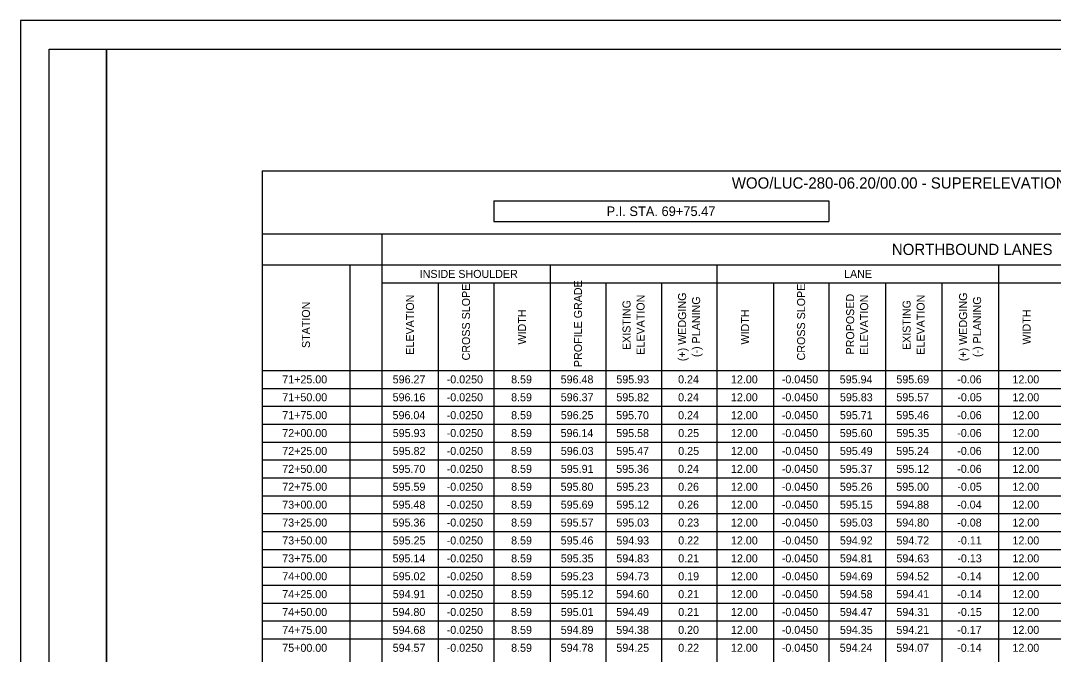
# Model space of a CAD drawing. Extents: x 0 to 34, y 0 to 22.
# Drawn here: x 0 to 18.07, y 10.92 to 22 of the extents above; entities that cross this region are included whole.
import ezdxf

# ---------------------------------------------------------------- set-up
doc = ezdxf.new("R2010")
doc.units = 0
for name, color, linetype in [('SH_Border', 7, 'Continuous'), ('SH_Cut_Line', 7, 'Continuous'), ('SH_Text', 7, 'Continuous')]:
    doc.layers.add(name, color=color, linetype=linetype)

msp = doc.modelspace()

# ---------------------------------------------------------------- linework, layer by layer
at = {"layer": 'SH_Border'}
for points in [[(0.5, 21.5), (1.5, 21.5), (1.5, 0.5), (0.5, 0.5)], [(1.5, 21.5), (33.5, 21.5), (33.5, 0.5), (1.5, 0.5)]]:
    msp.add_lwpolyline(points, close=True, dxfattribs=at)
at = {"layer": 'SH_Cut_Line'}
msp.add_lwpolyline([(0, 0), (34, 0), (34, 22), (0, 22)], close=True, dxfattribs=at)
at = {"layer": 'SH_Text'}
for p, q in [((4.225, 19.375), (29.277, 19.375)), ((4.225, 19.375), (4.225, 2.624)), ((8.277, 18.848), (14.14, 18.848)), ((8.277, 18.848), (8.277, 18.486)), ((14.14, 18.848), (14.14, 18.486)), ((8.277, 18.486), (14.14, 18.486)), ((4.225, 18.271), (29.277, 18.271)), ((6.317, 18.271), (6.317, 2.624)), ((4.225, 17.728), (29.277, 17.728)), ((5.757, 17.728), (5.757, 2.624)), ((9.265, 17.728), (9.265, 2.624)), ((12.18, 17.728), (12.18, 2.624)), ((17.105, 17.728), (17.105, 2.624)), ((6.317, 17.415), (26.954, 17.415)), ((7.305, 17.415), (7.305, 2.624)), ((8.277, 17.415), (8.277, 2.624)), ((10.237, 17.415), (10.237, 2.624)), ((11.209, 17.415), (11.209, 2.624)), ((13.169, 17.415), (13.169, 2.624)), ((14.14, 17.415), (14.14, 2.624)), ((15.129, 17.415), (15.129, 2.624)), ((16.117, 17.415), (16.117, 2.624)), ((4.225, 15.883), (29.277, 15.883)), ((4.225, 15.57), (29.277, 15.57)), ((4.225, 15.257), (29.277, 15.257)), ((4.225, 14.944), (29.277, 14.944)), ((4.225, 14.631), (29.277, 14.631)), ((4.225, 14.319), (29.277, 14.319)), ((4.225, 14.006), (29.277, 14.006)), ((4.225, 13.693), (29.277, 13.693)), ((4.225, 13.38), (29.277, 13.38)), ((4.225, 13.067), (29.277, 13.067)), ((4.225, 12.754), (29.277, 12.754)), ((4.225, 12.441), (29.277, 12.441)), ((4.225, 12.128), (29.277, 12.128)), ((4.225, 11.815), (29.277, 11.815)), ((4.225, 11.502), (29.277, 11.502)), ((4.225, 11.189), (29.277, 11.189))]:
    msp.add_line(p, q, dxfattribs=at)

# ---------------------------------------------------------------- texts
for s, height, p in [('WOO/LUC-280-06.20/00.00 - SUPERELEVATION TABLE', 0.196, (12.442, 19.063)), ('P.I. STA. 69+75.47', 0.168, (10.251, 18.583)), ('NORTHBOUND LANES', 0.196, (15.242, 17.902)), ('INSIDE SHOULDER', 0.14, (6.981, 17.501)), ('LANE', 0.14, (14.406, 17.501)), ('71+25.00', 0.14, (4.577, 15.657)), ('596.27', 0.14, (6.509, 15.657)), ('-0.0250', 0.14, (7.454, 15.657)), ('8.59', 0.14, (8.581, 15.657)), ('596.48', 0.14, (9.448, 15.657)), ('595.93', 0.14, (10.422, 15.657)), ('0.24', 0.14, (11.502, 15.657)), ('12.00', 0.14, (12.427, 15.657)), ('-0.0450', 0.14, (13.317, 15.657)), ('595.94', 0.14, (14.33, 15.657)), ('595.69', 0.14, (15.321, 15.657)), ('-0.06', 0.14, (16.386, 15.657)), ('12.00', 0.14, (17.352, 15.657)), ('71+50.00', 0.14, (4.577, 15.344)), ('596.16', 0.14, (6.508, 15.344)), ('-0.0250', 0.14, (7.454, 15.344)), ('8.59', 0.14, (8.581, 15.344)), ('596.37', 0.14, (9.449, 15.344)), ('595.82', 0.14, (10.422, 15.344)), ('0.24', 0.14, (11.502, 15.344)), ('12.00', 0.14, (12.427, 15.344)), ('-0.0450', 0.14, (13.317, 15.344)), ('595.83', 0.14, (14.334, 15.344)), ('595.57', 0.14, (15.321, 15.344)), ('-0.05', 0.14, (16.388, 15.344)), ('12.00', 0.14, (17.352, 15.344)), ('71+75.00', 0.14, (4.577, 15.031)), ('596.04', 0.14, (6.507, 15.031)), ('-0.0250', 0.14, (7.454, 15.031)), ('8.59', 0.14, (8.581, 15.031)), ('596.25', 0.14, (9.45, 15.031)), ('595.70', 0.14, (10.419, 15.031)), ('0.24', 0.14, (11.502, 15.031)), ('12.00', 0.14, (12.427, 15.031)), ('-0.0450', 0.14, (13.317, 15.031)), ('595.71', 0.14, (14.333, 15.031)), ('595.46', 0.14, (15.32, 15.031)), ('-0.06', 0.14, (16.386, 15.031)), ('12.00', 0.14, (17.352, 15.031)), ('72+00.00', 0.14, (4.577, 14.718)), ('595.93', 0.14, (6.51, 14.718)), ('-0.0250', 0.14, (7.454, 14.718)), ('8.59', 0.14, (8.581, 14.718)), ('596.14', 0.14, (9.447, 14.718)), ('595.58', 0.14, (10.42, 14.718)), ('0.25', 0.14, (11.505, 14.718)), ('12.00', 0.14, (12.427, 14.718)), ('-0.0450', 0.14, (13.317, 14.718)), ('595.60', 0.14, (14.331, 14.718)), ('595.35', 0.14, (15.322, 14.718)), ('-0.06', 0.14, (16.386, 14.718)), ('12.00', 0.14, (17.352, 14.718)), ('72+25.00', 0.14, (4.577, 14.405)), ('595.82', 0.14, (6.51, 14.405)), ('-0.0250', 0.14, (7.454, 14.405)), ('8.59', 0.14, (8.581, 14.405)), ('596.03', 0.14, (9.45, 14.405)), ('595.47', 0.14, (10.421, 14.405)), ('0.25', 0.14, (11.505, 14.405)), ('12.00', 0.14, (12.427, 14.405)), ('-0.0450', 0.14, (13.317, 14.405)), ('595.49', 0.14, (14.333, 14.405)), ('595.24', 0.14, (15.319, 14.405)), ('-0.06', 0.14, (16.386, 14.405)), ('12.00', 0.14, (17.352, 14.405)), ('72+50.00', 0.14, (4.577, 14.092)), ('595.70', 0.14, (6.507, 14.092)), ('-0.0250', 0.14, (7.454, 14.092)), ('8.59', 0.14, (8.581, 14.092)), ('595.91', 0.14, (9.45, 14.092)), ('595.36', 0.14, (10.42, 14.092)), ('0.24', 0.14, (11.502, 14.092)), ('12.00', 0.14, (12.427, 14.092)), ('-0.0450', 0.14, (13.317, 14.092)), ('595.37', 0.14, (14.332, 14.092)), ('595.12', 0.14, (15.322, 14.092)), ('-0.06', 0.14, (16.386, 14.092)), ('12.00', 0.14, (17.352, 14.092)), ('72+75.00', 0.14, (4.577, 13.779)), ('595.59', 0.14, (6.509, 13.779)), ('-0.0250', 0.14, (7.454, 13.779)), ('8.59', 0.14, (8.581, 13.779)), ('595.80', 0.14, (9.447, 13.779)), ('595.23', 0.14, (10.422, 13.779)), ('0.26', 0.14, (11.503, 13.779)), ('12.00', 0.14, (12.427, 13.779)), ('-0.0450', 0.14, (13.317, 13.779)), ('595.26', 0.14, (14.332, 13.779)), ('595.00', 0.14, (15.319, 13.779)), ('-0.05', 0.14, (16.388, 13.779)), ('12.00', 0.14, (17.352, 13.779)), ('73+00.00', 0.14, (4.577, 13.466)), ('595.48', 0.14, (6.508, 13.466)), ('-0.0250', 0.14, (7.454, 13.466)), ('8.59', 0.14, (8.581, 13.466)), ('595.69', 0.14, (9.449, 13.466)), ('595.12', 0.14, (10.422, 13.466)), ('0.26', 0.14, (11.503, 13.466)), ('12.00', 0.14, (12.427, 13.466)), ('-0.0450', 0.14, (13.317, 13.466)), ('595.15', 0.14, (14.334, 13.466)), ('594.88', 0.14, (15.32, 13.466)), ('-0.04', 0.14, (16.385, 13.466)), ('12.00', 0.14, (17.352, 13.466)), ('73+25.00', 0.14, (4.577, 13.153)), ('595.36', 0.14, (6.508, 13.153)), ('-0.0250', 0.14, (7.454, 13.153)), ('8.59', 0.14, (8.581, 13.153)), ('595.57', 0.14, (9.449, 13.153)), ('595.03', 0.14, (10.422, 13.153)), ('0.23', 0.14, (11.506, 13.153)), ('12.00', 0.14, (12.427, 13.153)), ('-0.0450', 0.14, (13.317, 13.153)), ('595.03', 0.14, (14.334, 13.153)), ('594.80', 0.14, (15.319, 13.153)), ('-0.08', 0.14, (16.386, 13.153)), ('12.00', 0.14, (17.352, 13.153)), ('73+50.00', 0.14, (4.577, 12.84)), ('595.25', 0.14, (6.51, 12.84)), ('-0.0250', 0.14, (7.454, 12.84)), ('8.59', 0.14, (8.581, 12.84)), ('595.46', 0.14, (9.448, 12.84)), ('594.93', 0.14, (10.422, 12.84)), ('0.22', 0.14, (11.505, 12.84)), ('12.00', 0.14, (12.427, 12.84)), ('-0.0450', 0.14, (13.317, 12.84)), ('594.92', 0.14, (14.333, 12.84)), ('594.72', 0.14, (15.322, 12.84)), ('-0.11', 0.14, (16.388, 12.84)), ('12.00', 0.14, (17.352, 12.84)), ('73+75.00', 0.14, (4.577, 12.527)), ('595.14', 0.14, (6.507, 12.527)), ('-0.0250', 0.14, (7.454, 12.527)), ('8.59', 0.14, (8.581, 12.527)), ('595.35', 0.14, (9.45, 12.527)), ('594.83', 0.14, (10.422, 12.527)), ('0.21', 0.14, (11.505, 12.527)), ('12.00', 0.14, (12.427, 12.527)), ('-0.0450', 0.14, (13.317, 12.527)), ('594.81', 0.14, (14.333, 12.527)), ('594.63', 0.14, (15.322, 12.527)), ('-0.13', 0.14, (16.388, 12.527)), ('12.00', 0.14, (17.352, 12.527)), ('74+00.00', 0.14, (4.577, 12.214)), ('595.02', 0.14, (6.51, 12.214)), ('-0.0250', 0.14, (7.454, 12.214)), ('8.59', 0.14, (8.581, 12.214)), ('595.23', 0.14, (9.45, 12.214)), ('594.73', 0.14, (10.422, 12.214)), ('0.19', 0.14, (11.505, 12.214)), ('12.00', 0.14, (12.427, 12.214)), ('-0.0450', 0.14, (13.317, 12.214)), ('594.69', 0.14, (14.333, 12.214)), ('594.52', 0.14, (15.322, 12.214)), ('-0.14', 0.14, (16.385, 12.214)), ('12.00', 0.14, (17.352, 12.214)), ('74+25.00', 0.14, (4.577, 11.901)), ('594.91', 0.14, (6.51, 11.901)), ('-0.0250', 0.14, (7.454, 11.901)), ('8.59', 0.14, (8.581, 11.901)), ('595.12', 0.14, (9.45, 11.901)), ('594.60', 0.14, (10.419, 11.901)), ('0.21', 0.14, (11.505, 11.901)), ('12.00', 0.14, (12.427, 11.901)), ('-0.0450', 0.14, (13.317, 11.901)), ('594.58', 0.14, (14.332, 11.901)), ('594.41', 0.14, (15.321, 11.901)), ('-0.14', 0.14, (16.385, 11.901)), ('12.00', 0.14, (17.352, 11.901)), ('74+50.00', 0.14, (4.577, 11.589)), ('594.80', 0.14, (6.507, 11.589)), ('-0.0250', 0.14, (7.454, 11.589)), ('8.59', 0.14, (8.581, 11.589)), ('595.01', 0.14, (9.45, 11.589)), ('594.49', 0.14, (10.421, 11.589)), ('0.21', 0.14, (11.505, 11.589)), ('12.00', 0.14, (12.427, 11.589)), ('-0.0450', 0.14, (13.317, 11.589)), ('594.47', 0.14, (14.332, 11.589)), ('594.31', 0.14, (15.321, 11.589)), ('-0.15', 0.14, (16.388, 11.589)), ('12.00', 0.14, (17.352, 11.589)), ('74+75.00', 0.14, (4.577, 11.276)), ('594.68', 0.14, (6.508, 11.276)), ('-0.0250', 0.14, (7.454, 11.276)), ('8.59', 0.14, (8.581, 11.276)), ('594.89', 0.14, (9.449, 11.276)), ('594.38', 0.14, (10.42, 11.276)), ('0.20', 0.14, (11.503, 11.276)), ('12.00', 0.14, (12.427, 11.276)), ('-0.0450', 0.14, (13.317, 11.276)), ('594.35', 0.14, (14.334, 11.276)), ('594.21', 0.14, (15.321, 11.276)), ('-0.17', 0.14, (16.387, 11.276)), ('12.00', 0.14, (17.352, 11.276)), ('75+00.00', 0.14, (4.577, 10.963)), ('594.57', 0.14, (6.509, 10.963)), ('-0.0250', 0.14, (7.454, 10.963)), ('8.59', 0.14, (8.581, 10.963)), ('594.78', 0.14, (9.448, 10.963)), ('594.25', 0.14, (10.422, 10.963)), ('0.22', 0.14, (11.505, 10.963)), ('12.00', 0.14, (12.427, 10.963)), ('-0.0450', 0.14, (13.317, 10.963)), ('594.24', 0.14, (14.33, 10.963)), ('594.07', 0.14, (15.321, 10.963)), ('-0.14', 0.14, (16.385, 10.963)), ('12.00', 0.14, (17.352, 10.963))]:
    msp.add_text(s, height=height, dxfattribs=at).set_placement(p)
for s, p in [('CROSS SLOPE', (7.861, 16.058)), ('PROFILE GRADE', (9.821, 15.941)), ('CROSS SLOPE', (13.724, 16.058)), ('ELEVATION', (6.881, 16.158)), ('ELEVATION', (10.915, 16.158)), ('(+) WEDGING', (11.642, 16.045)), ('(-) PLANING', (11.887, 16.117)), ('PROPOSED ', (14.582, 16.162)), ('ELEVATION', (14.827, 16.158)), ('ELEVATION', (15.815, 16.158)), ('(+) WEDGING', (16.558, 16.045)), ('(-) PLANING', (16.803, 16.117)), ('STATION', (5.061, 16.275)), ('EXISTING ', (10.67, 16.24)), ('EXISTING ', (15.57, 16.24)), ('WIDTH', (8.841, 16.336)), ('WIDTH', (12.744, 16.336)), ('WIDTH', (17.669, 16.336))]:
    msp.add_text(s, height=0.14, rotation=90, dxfattribs=at).set_placement(p)

doc.saveas('drawing.dxf')
